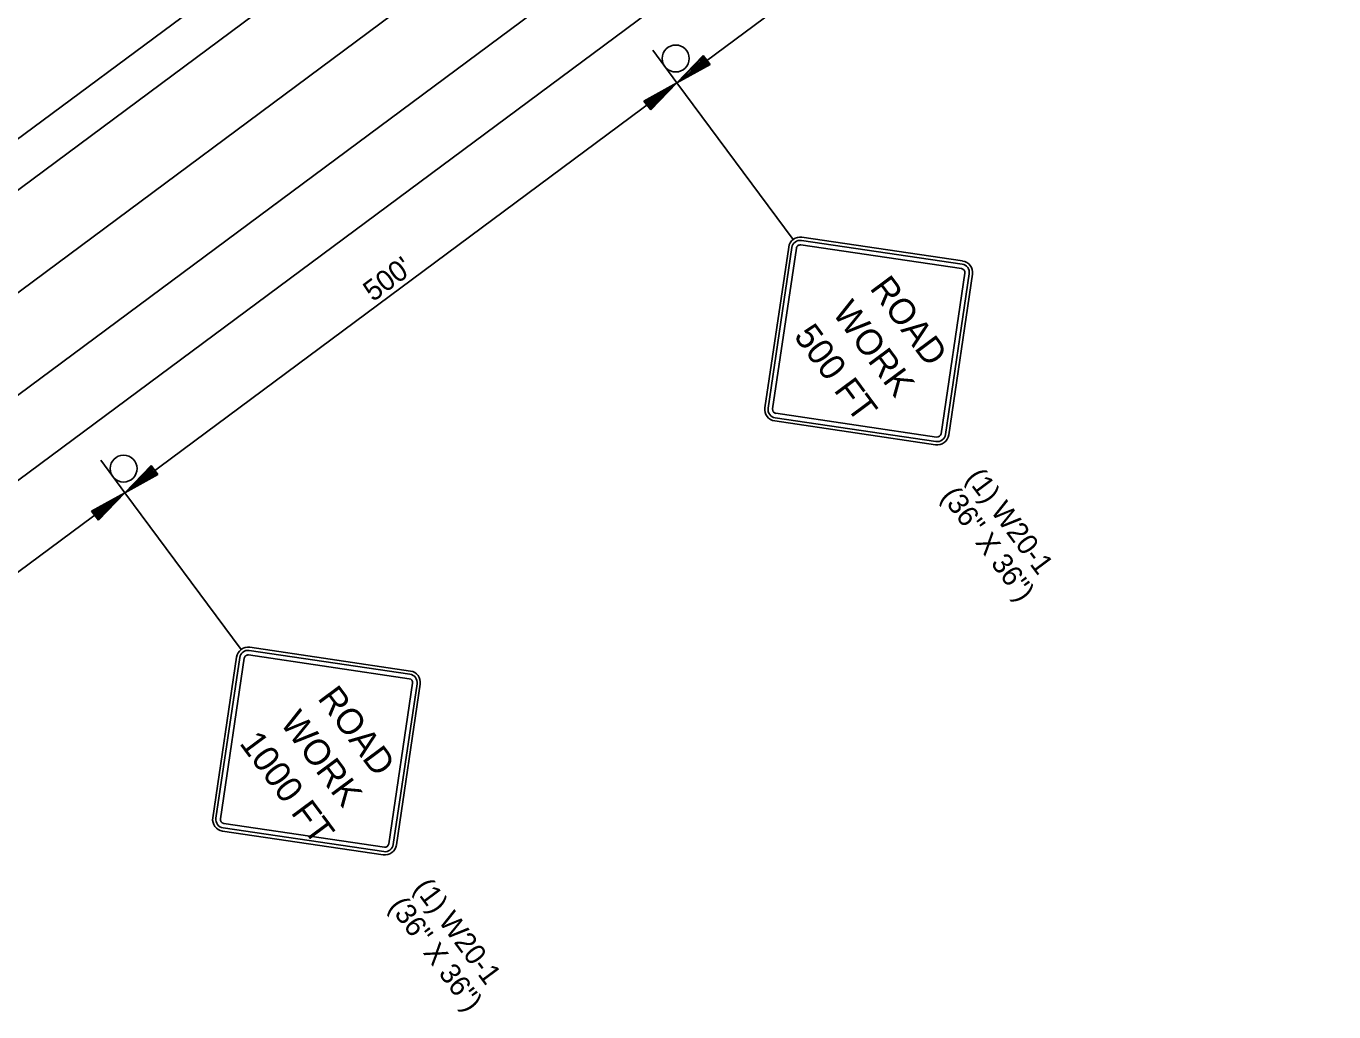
# Model space of a CAD drawing. Extents: x 998982 to 1000626, y 1875366 to 1876934.
# Drawn here: x 999363.4 to 999743.7, y 1875480.6 to 1875767.2 of the extents above; entities that cross this region are included whole.
import ezdxf

# ---------------------------------------------------------------- set-up
doc = ezdxf.new("R2010")
doc.units = 0
for name, color, linetype in [('P_TC_Signs_Temporary', 7, 'Continuous'), ('R_Border Prem', 7, 'Continuous'), ('R_Draft', 7, 'Continuous'), ('STAMP', 7, 'Continuous')]:
    doc.layers.add(name, color=color, linetype=linetype)

msp = doc.modelspace()

# ---------------------------------------------------------------- linework, layer by layer
at = {"layer": 'P_TC_Signs_Temporary'}
for p, q in [((999588.68, 1875703.61), (999635.42, 1875696.7)), ((999588.87, 1875704.91), (999635.61, 1875698)), ((999589, 1875705.83), (999635.75, 1875698.93)), ((999578.27, 1875656.25), (999585.17, 1875702.99)), ((999579.19, 1875656.11), (999586.1, 1875702.85)), ((999580.49, 1875655.92), (999587.4, 1875702.66)), ((999636.37, 1875695.42), (999629.46, 1875648.68)), ((999637.66, 1875695.23), (999630.76, 1875648.49)), ((999638.59, 1875695.1), (999631.69, 1875648.35)), ((999628.18, 1875647.73), (999581.44, 1875654.64)), ((999627.85, 1875645.51), (999581.11, 1875652.41)), ((999627.99, 1875646.43), (999581.25, 1875653.34)), ((999428.29, 1875585.67), (999475.04, 1875578.77)), ((999428.43, 1875586.6), (999475.17, 1875579.7)), ((999417.69, 1875537.01), (999424.6, 1875583.76)), ((999418.62, 1875536.88), (999425.53, 1875583.62)), ((999419.92, 1875536.68), (999426.82, 1875583.43)), ((999428.1, 1875584.38), (999474.84, 1875577.47)), ((999475.79, 1875576.19), (999468.89, 1875529.45)), ((999477.09, 1875576), (999470.19, 1875529.26)), ((999478.02, 1875575.86), (999471.11, 1875529.12)), ((999467.28, 1875526.28), (999420.54, 1875533.18)), ((999467.42, 1875527.2), (999420.68, 1875534.11)), ((999467.61, 1875528.5), (999420.87, 1875535.41))]:
    msp.add_line(p, q, dxfattribs=at)
for centre, radius, start, end in [((999588.51, 1875702.49), 3.38, 81.5953, 171.5953), ((999588.51, 1875702.49), 2.44, 81.5953, 171.5953), ((999588.51, 1875702.49), 1.12, 81.5953, 171.5953), ((999635.25, 1875695.59), 1.13, 351.5953, 81.5953), ((999635.25, 1875695.59), 2.44, 351.5953, 81.5953), ((999635.25, 1875695.59), 3.37, 351.5953, 81.5953), ((999581.6, 1875655.75), 3.37, 171.5953, 261.5953), ((999581.6, 1875655.75), 2.44, 171.5953, 261.5953), ((999581.6, 1875655.75), 1.13, 171.5953, 261.5953), ((999628.35, 1875648.85), 3.38, 261.5953, 351.5953), ((999628.35, 1875648.85), 2.44, 261.5953, 351.5953), ((999628.35, 1875648.85), 1.12, 261.5953, 351.5953), ((999427.94, 1875583.26), 3.38, 81.5953, 171.5953), ((999427.94, 1875583.26), 2.44, 81.5953, 171.5953), ((999427.94, 1875583.26), 1.12, 81.5953, 171.5953), ((999474.68, 1875576.36), 2.44, 351.5953, 81.5953), ((999474.68, 1875576.36), 3.37, 351.5953, 81.5953), ((999474.68, 1875576.36), 1.13, 351.5953, 81.5953), ((999421.03, 1875536.52), 3.37, 171.5953, 261.5953), ((999421.03, 1875536.52), 2.44, 171.5953, 261.5953), ((999421.03, 1875536.52), 1.13, 171.5953, 261.5953), ((999467.77, 1875529.61), 3.38, 261.5953, 351.5953), ((999467.77, 1875529.61), 2.44, 261.5953, 351.5953), ((999467.77, 1875529.61), 1.12, 261.5953, 351.5953)]:
    msp.add_arc(centre, radius, start, end, dxfattribs=at)
at = {"layer": 'R_Draft'}
for p, q in [((999192.61, 1875564.71), (999743.69, 1875973.9)), ((999171.2, 1875593.53), (999643.2, 1875944.01)), ((999178.34, 1875583.93), (999650.33, 1875934.4)), ((999206.88, 1875545.49), (999678.87, 1875895.96)), ((999218.77, 1875529.47), (999690.77, 1875879.94)), ((999713.25, 1875869.99), (999552.67, 1875750.76)), ((999560.31, 1875758.68), (999552.67, 1875750.76)), ((999560.48, 1875758.46), (999554.11, 1875751.87)), ((999560.65, 1875758.24), (999555.6, 1875753)), ((999560.81, 1875758.03), (999557.03, 1875754.11)), ((999561.79, 1875756.74), (999557.03, 1875754.11)), ((999560.98, 1875757.81), (999558.5, 1875755.23)), ((999561.62, 1875756.97), (999558.5, 1875755.23)), ((999561.15, 1875757.59), (999559.94, 1875756.34)), ((999561.46, 1875757.18), (999559.94, 1875756.34)), ((999562.29, 1875756.09), (999560.31, 1875758.68)), ((999562.29, 1875756.09), (999552.67, 1875750.76)), ((999562.13, 1875756.3), (999554.11, 1875751.87)), ((999561.96, 1875756.53), (999555.6, 1875753)), ((999552.67, 1875750.76), (999392.1, 1875631.53)), ((999543.05, 1875745.43), (999552.67, 1875750.76)), ((999543.22, 1875745.21), (999551.23, 1875749.65)), ((999544.87, 1875743.05), (999551.23, 1875749.65)), ((999545.04, 1875742.84), (999552.67, 1875750.76)), ((999552.67, 1875750.76), (999586.5, 1875705.2)), ((999543.05, 1875745.43), (999545.04, 1875742.84)), ((999543.38, 1875744.99), (999549.75, 1875748.51)), ((999543.55, 1875744.78), (999548.31, 1875747.41)), ((999543.72, 1875744.55), (999546.85, 1875746.29)), ((999544.37, 1875743.71), (999546.85, 1875746.29)), ((999544.54, 1875743.49), (999548.31, 1875747.41)), ((999544.7, 1875743.28), (999549.75, 1875748.51)), ((999543.89, 1875744.34), (999545.41, 1875745.18)), ((999544.2, 1875743.93), (999545.41, 1875745.18)), ((999399.74, 1875639.45), (999392.1, 1875631.53)), ((999399.9, 1875639.23), (999393.54, 1875632.64)), ((999400.07, 1875639.01), (999395.02, 1875633.77)), ((999400.24, 1875638.8), (999396.46, 1875634.88)), ((999401.72, 1875636.86), (999399.74, 1875639.45)), ((999401.72, 1875636.86), (999392.1, 1875631.53)), ((999401.56, 1875637.07), (999393.54, 1875632.64)), ((999401.39, 1875637.29), (999395.02, 1875633.77)), ((999401.22, 1875637.51), (999396.46, 1875634.88)), ((999400.41, 1875638.58), (999397.93, 1875636)), ((999401.05, 1875637.73), (999397.93, 1875636)), ((999400.57, 1875638.36), (999399.37, 1875637.11)), ((999400.89, 1875637.95), (999399.37, 1875637.11)), ((999392.1, 1875631.53), (999231.53, 1875512.3)), ((999382.48, 1875626.2), (999392.1, 1875631.53)), ((999384.46, 1875623.6), (999392.1, 1875631.53)), ((999392.1, 1875631.53), (999425.93, 1875585.97)), ((999382.64, 1875625.98), (999390.66, 1875630.42)), ((999382.81, 1875625.76), (999389.17, 1875629.28)), ((999382.98, 1875625.55), (999387.74, 1875628.18)), ((999383.96, 1875624.26), (999387.74, 1875628.18)), ((999384.13, 1875624.04), (999389.17, 1875629.28)), ((999384.3, 1875623.82), (999390.66, 1875630.42)), ((999382.48, 1875626.2), (999384.46, 1875623.6)), ((999383.15, 1875625.32), (999386.27, 1875627.05)), ((999383.31, 1875625.11), (999384.84, 1875625.95)), ((999383.62, 1875624.7), (999384.84, 1875625.95)), ((999383.79, 1875624.48), (999386.27, 1875627.05))]:
    msp.add_line(p, q, dxfattribs=at)
at = {"layer": 'STAMP'}
for p, q in [((999552.67, 1875750.76), (999545.67, 1875760.2)), ((999392.1, 1875631.53), (999385.1, 1875640.97))]:
    msp.add_line(p, q, dxfattribs=at)
for centre in [(999552.32, 1875757.81), (999391.75, 1875638.58)]:
    msp.add_circle(centre, 3.92, dxfattribs=at)

# ---------------------------------------------------------------- texts
at = {"layer": 'P_TC_Signs_Temporary'}
for s, p in [(' ROAD ', (999606.87, 1875693.22)), ('WORK', (999597.63, 1875683.83)), ('500 FT ', (999586.44, 1875677.04)), (' ROAD ', (999446.3, 1875573.99)), ('WORK', (999437.05, 1875564.6)), ('1000 FT', (999425.23, 1875558.68))]:
    msp.add_text(s, height=7.5, rotation=306.5953, dxfattribs=at).set_placement(p)
at = {"layer": 'R_Border Prem'}
for s, rotation, p in [("500'", 36.5953, (999464.29, 1875686.91)), ('(1) W20-1', 306.5953, (999636.49, 1875635.86)), ('(36" X 36")', 306.5953, (999629.27, 1875630.5)), ('(1) W20-1', 306.5953, (999475.92, 1875516.63)), ('(36" X 36")', 306.5953, (999468.69, 1875511.26))]:
    msp.add_text(s, height=6, rotation=rotation, dxfattribs=at).set_placement(p)

doc.saveas('drawing.dxf')
